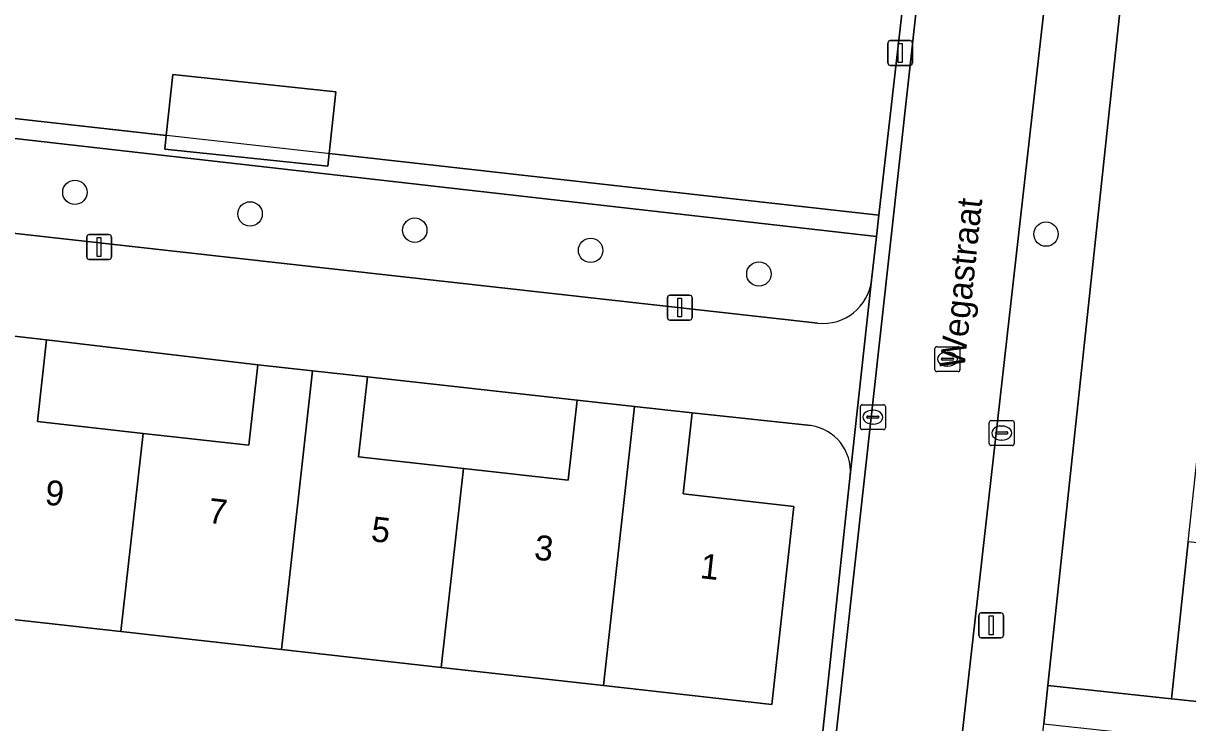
# Model space of a CAD drawing. Extents: x 161928 to 163071, y 386474 to 387428.
# Drawn here: x 162131.24 to 162177.94, y 386955.11 to 386983.15 of the extents above; entities that cross this region are included whole.
import ezdxf

# ---------------------------------------------------------------- set-up
doc = ezdxf.new("R2010")
doc.units = 0
for name, color, linetype in [('IMGEO_Boom', 7, 'Continuous'), ('IMGEO_Erf', 7, 'Continuous'), ('IMGEO_Groenvoorziening', 7, 'Continuous'), ('IMGEO_Haag', 7, 'Continuous'), ('IMGEO_Kolk', 7, 'Continuous'), ('IMGEO_Lichtmast', 7, 'Continuous'), ('IMGEO_Openbare_ruimte_label', 7, 'Continuous'), ('IMGEO_Pand', 7, 'Continuous'), ('IMGEO_Pand_nummerreeks', 7, 'Continuous'), ('IMGEO_Rijbaan_lokaal_open', 7, 'Continuous'), ('IMGEO_Rioolput', 7, 'Continuous'), ('IMGEO_Voetpad_open', 7, 'Continuous')]:
    doc.layers.add(name, color=color, linetype=linetype)

msp = doc.modelspace()

# ---------------------------------------------------------------- linework, layer by layer
at = {"layer": 'IMGEO_Boom'}
for centre in [(162133.311, 386976.375), (162140.338, 386975.511), (162146.943, 386974.86), (162172.257, 386974.701), (162153.993, 386974.049), (162160.742, 386973.102)]:
    msp.add_circle(centre, 0.489, dxfattribs=at)
at = {"layer": 'IMGEO_Erf'}
for points in [[(162179.889, 386980.353), (162180.525, 386986.295), (162181.184, 386992.453), (162181.804, 386998.248), (162181.992, 387000), (162182.414, 387003.937), (162177.44, 387004.467), (162176.963, 387000), (162172.334, 386956.598), (162177.289, 386956.069), (162177.963, 386962.367), (162178.601, 386968.327), (162179.255, 386974.437)], [(162132.178, 386970.465), (162131.811, 386967.181), (162136.048, 386966.707), (162140.285, 386966.233), (162140.646, 386969.464)], [(162145.047, 386968.972), (162144.69, 386965.776), (162148.892, 386965.306), (162153.093, 386964.836), (162153.452, 386968.047)]]:
    msp.add_lwpolyline(points, close=True, dxfattribs=at)
for points in [[(162131.63, 386987.411), (162125.153, 386988.143), (162118.693, 386988.873), (162109.184, 386989.948), (162108.279, 386981.822), (162117.837, 386980.804), (162130.648, 386979.367), (162136.977, 386978.659), (162137.235, 386981.096), (162143.771, 386980.405), (162143.509, 386977.927), (162165.555, 386975.46), (162167.511, 386992.682)], [(162162.828, 386967.021), (162158.07, 386967.531), (162157.707, 386964.281), (162162.148, 386963.785), (162161.259, 386955.842), (162154.507, 386956.597), (162147.999, 386957.326), (162141.594, 386958.042), (162135.159, 386958.762), (162128.668, 386959.489), (162122.196, 386960.213), (162115.733, 386960.936), (162108.941, 386961.696), (162109.832, 386969.663), (162114.38, 386969.154), (162114.747, 386972.438), (162109.157, 386973.068)], [(162106.981, 386971.336), (162105.127, 386954.086), (162111.551, 386953.32), (162111.902, 386956.457), (162115.148, 386956.094), (162114.794, 386952.933), (162162.272, 386947.379), (162162.618, 386948.375), (162164.401, 386965.029)]]:
    msp.add_lwpolyline(points, dxfattribs=at)
msp.add_arc((162162.57, 386965.2), 1.839, 354.6685, 81.9249, dxfattribs=at)
at = {"layer": 'IMGEO_Groenvoorziening'}
msp.add_lwpolyline([(162136.977, 386978.659), (162130.648, 386979.367), (162117.837, 386980.804), (162108.279, 386981.822), (162108.2, 386981.114), (162165.458, 386974.606), (162165.555, 386975.46), (162143.509, 386977.927), (162143.456, 386977.421), (162136.919, 386978.111)], close=True, dxfattribs=at)
for points in [[(162165.259, 386972.856), (162165.458, 386974.606), (162108.2, 386981.114)], [(162109.769, 386977.086), (162163.103, 386971.136)]]:
    msp.add_lwpolyline(points, dxfattribs=at)
msp.add_arc((162163.32, 386973.075), 1.952, 263.6208, 353.5431, dxfattribs=at)
at = {"layer": 'IMGEO_Haag'}
msp.add_lwpolyline([(162108.279, 386981.822), (162108.2, 386981.114), (162165.458, 386974.606), (162165.555, 386975.46), (162130.648, 386979.367), (162117.837, 386980.804)], close=True, dxfattribs=at)
at = {"layer": 'IMGEO_Kolk'}
for p, q in [((162164.89, 386967.862), (162165.742, 386967.862)), ((162164.815, 386966.936), (162164.815, 386967.788)), ((162165.074, 386967.356), (162165.074, 386967.368)), ((162165.117, 386967.405), (162165.515, 386967.405)), ((162165.303, 386967.642), (162165.328, 386967.642)), ((162165.558, 386967.368), (162165.558, 386967.356)), ((162165.816, 386967.788), (162165.816, 386966.936)), ((162165.512, 386967.319), (162165.114, 386967.319)), ((162165.326, 386967.082), (162165.301, 386967.082)), ((162169.978, 386966.299), (162169.978, 386967.151)), ((162170.053, 386967.225), (162170.905, 386967.225)), ((162170.466, 386967.005), (162170.491, 386967.005)), ((162170.979, 386967.151), (162170.979, 386966.299)), ((162165.742, 386966.862), (162164.89, 386966.862)), ((162170.237, 386966.719), (162170.237, 386966.731)), ((162170.675, 386966.682), (162170.277, 386966.682)), ((162170.28, 386966.768), (162170.678, 386966.768)), ((162170.489, 386966.445), (162170.464, 386966.445)), ((162170.721, 386966.731), (162170.721, 386966.719)), ((162170.905, 386966.225), (162170.053, 386966.225))]:
    msp.add_line(p, q, dxfattribs=at)
for points in [[(162164.89, 386967.862), (162165.742, 386967.862)], [(162164.815, 386966.936), (162164.815, 386967.788)], [(162165.816, 386967.788), (162165.816, 386966.936)], [(162169.978, 386966.299), (162169.978, 386967.151)], [(162170.053, 386967.225), (162170.905, 386967.225)], [(162170.979, 386967.151), (162170.979, 386966.299)], [(162165.742, 386966.862), (162164.89, 386966.862)], [(162170.905, 386966.225), (162170.053, 386966.225)]]:
    msp.add_lwpolyline(points, dxfattribs=at)
for centre, radius, start, end in [((162164.892, 386967.786), 0.0765, 91.552, 178.448), ((162164.892, 386967.786), 0.0765, 91.552, 178.448), ((162165.74, 386967.786), 0.0765, 1.552, 88.448), ((162165.74, 386967.786), 0.0765, 1.552, 88.448), ((162165.114, 386967.365), 0.0403, 85.8775, 175.7526), ((162165.519, 386967.367), 0.0386, 1.7309, 96.639), ((162164.892, 386966.938), 0.0765, 181.552, 268.448), ((162164.892, 386966.938), 0.0765, 181.552, 268.448), ((162165.111, 386967.355), 0.0366, 178.938, 274.7102), ((162165.515, 386967.362), 0.043, 264.8664, 352.4533), ((162165.74, 386966.938), 0.0765, 271.552, 358.448), ((162165.74, 386966.938), 0.0765, 271.552, 358.448), ((162170.055, 386967.149), 0.0765, 91.552, 178.448), ((162170.055, 386967.149), 0.0765, 91.552, 178.448), ((162170.903, 386967.149), 0.0765, 1.552, 88.448), ((162170.903, 386967.149), 0.0765, 1.552, 88.448), ((162170.277, 386966.728), 0.0403, 85.8775, 175.7526), ((162170.274, 386966.718), 0.0366, 178.938, 274.7102), ((162170.678, 386966.725), 0.043, 264.8664, 352.4533), ((162170.682, 386966.73), 0.0386, 1.7309, 96.639), ((162170.055, 386966.301), 0.0765, 181.552, 268.448), ((162170.055, 386966.301), 0.0765, 181.552, 268.448), ((162170.903, 386966.301), 0.0765, 271.552, 358.448), ((162170.903, 386966.301), 0.0765, 271.552, 358.448)]:
    msp.add_arc(centre, radius, start, end, dxfattribs=at)
for centre, major_axis, ratio, start_param, end_param in [((162165.302, 386967.362), (-0.387, 0.002), 0.722429, 4.712389, 7.853982), ((162165.327, 386967.362), (-0.39, 0.002), 0.717154, 1.570796, 4.712389), ((162170.465, 386966.725), (-0.387, 0.002), 0.722429, 4.712389, 7.853982), ((162170.49, 386966.725), (-0.39, 0.002), 0.717154, 1.570796, 4.712389)]:
    msp.add_ellipse(centre, major_axis=major_axis, ratio=ratio, start_param=start_param, end_param=end_param, dxfattribs=at)
at = {"layer": 'IMGEO_Lichtmast'}
for p, q in [((162165.912, 386981.563), (162165.912, 386982.363)), ((162165.912, 386982.363), (162165.912, 386981.563)), ((162166.012, 386982.463), (162166.802, 386982.463)), ((162166.802, 386982.463), (162166.012, 386982.463)), ((162166.902, 386982.363), (162166.902, 386981.563)), ((162166.902, 386981.563), (162166.902, 386982.363)), ((162166.802, 386981.463), (162166.012, 386981.463)), ((162166.012, 386981.463), (162166.802, 386981.463)), ((162133.786, 386973.785), (162133.786, 386974.585)), ((162133.786, 386974.585), (162133.786, 386973.785)), ((162133.886, 386974.685), (162134.676, 386974.685)), ((162134.676, 386974.685), (162133.886, 386974.685)), ((162134.776, 386974.585), (162134.776, 386973.785)), ((162134.776, 386973.785), (162134.776, 386974.585)), ((162134.676, 386973.685), (162133.886, 386973.685)), ((162133.886, 386973.685), (162134.676, 386973.685)), ((162157.072, 386971.354), (162157.072, 386972.154)), ((162157.072, 386972.154), (162157.072, 386971.354)), ((162157.172, 386972.254), (162157.962, 386972.254)), ((162157.962, 386972.254), (162157.172, 386972.254)), ((162158.062, 386972.154), (162158.062, 386971.354)), ((162158.062, 386971.354), (162158.062, 386972.154)), ((162157.962, 386971.254), (162157.172, 386971.254)), ((162157.172, 386971.254), (162157.962, 386971.254)), ((162169.661, 386959.514), (162170.451, 386959.514)), ((162170.451, 386959.514), (162169.661, 386959.514)), ((162169.561, 386958.614), (162169.561, 386959.414)), ((162169.561, 386959.414), (162169.561, 386958.614)), ((162170.551, 386959.414), (162170.551, 386958.614)), ((162170.551, 386958.614), (162170.551, 386959.414)), ((162170.451, 386958.514), (162169.661, 386958.514)), ((162169.661, 386958.514), (162170.451, 386958.514))]:
    msp.add_line(p, q, dxfattribs=at)
for points in [[(162166.332, 386982.338), (162166.482, 386982.338), (162166.482, 386981.588), (162166.332, 386981.588), (162166.332, 386982.338)], [(162134.206, 386974.56), (162134.356, 386974.56), (162134.356, 386973.81), (162134.206, 386973.81), (162134.206, 386974.56)], [(162157.492, 386972.129), (162157.642, 386972.129), (162157.642, 386971.379), (162157.492, 386971.379), (162157.492, 386972.129)], [(162169.981, 386959.389), (162170.131, 386959.389), (162170.131, 386958.639), (162169.981, 386958.639), (162169.981, 386959.389)]]:
    msp.add_lwpolyline(points, dxfattribs=at)
for centre, start, end in [((162166.012, 386982.363), 90, 180), ((162166.012, 386982.363), 90, 180), ((162166.802, 386982.363), 0, 90), ((162166.802, 386982.363), 360, 90), ((162166.012, 386981.563), 180, 270), ((162166.012, 386981.563), 180, 270), ((162166.802, 386981.563), 270, 0), ((162166.802, 386981.563), 270, 0), ((162133.886, 386974.585), 90, 180), ((162133.886, 386974.585), 90, 180), ((162134.676, 386974.585), 0, 90), ((162134.676, 386974.585), 360, 90), ((162133.886, 386973.785), 180, 270), ((162133.886, 386973.785), 180, 270), ((162134.676, 386973.785), 270, 0), ((162134.676, 386973.785), 270, 0), ((162157.172, 386972.154), 90, 180), ((162157.172, 386972.154), 90, 180), ((162157.962, 386972.154), 0, 90), ((162157.962, 386972.154), 360, 90), ((162157.172, 386971.354), 180, 270), ((162157.172, 386971.354), 180, 270), ((162157.962, 386971.354), 270, 0), ((162157.962, 386971.354), 270, 0), ((162169.661, 386959.414), 90, 180), ((162169.661, 386959.414), 90, 180), ((162170.451, 386959.414), 0, 90), ((162170.451, 386959.414), 360, 90), ((162169.661, 386958.614), 180, 270), ((162169.661, 386958.614), 180, 270), ((162170.451, 386958.614), 270, 0), ((162170.451, 386958.614), 270, 0)]:
    msp.add_arc(centre, 0.1, start, end, dxfattribs=at)
at = {"layer": 'IMGEO_Pand'}
for points in [[(162137.235, 386981.096), (162136.977, 386978.659), (162136.919, 386978.111), (162143.456, 386977.421), (162143.509, 386977.927), (162143.771, 386980.405)], [(162129.925, 386970.717), (162128.668, 386959.489), (162135.159, 386958.762), (162136.048, 386966.707), (162131.811, 386967.181), (162132.178, 386970.465)], [(162140.646, 386969.464), (162140.285, 386966.233), (162136.048, 386966.707), (162135.159, 386958.762), (162141.594, 386958.042), (162142.845, 386969.218)], [(162142.845, 386969.218), (162141.594, 386958.042), (162147.999, 386957.326), (162148.892, 386965.306), (162144.69, 386965.776), (162145.047, 386968.972)], [(162153.452, 386968.047), (162153.093, 386964.836), (162148.892, 386965.306), (162147.999, 386957.326), (162154.507, 386956.597), (162155.76, 386967.789)], [(162155.76, 386967.789), (162154.507, 386956.597), (162161.259, 386955.842), (162162.148, 386963.785), (162157.707, 386964.281), (162158.07, 386967.531)], [(162177.963, 386962.367), (162177.289, 386956.069), (162182.261, 386955.54), (162185.872, 386955.155), (162186.546, 386961.449)]]:
    msp.add_lwpolyline(points, close=True, dxfattribs=at)
at = {"layer": 'IMGEO_Rijbaan_lokaal_open'}
msp.add_lwpolyline([(162177.594, 387078.928), (162177.465, 387077.766), (162163.864, 386954.91), (162163.382, 386950.665), (162168.395, 386950.077), (162168.956, 386955.24), (162174.417, 387003.525), (162174.44, 387003.78), (162174.518, 387004.265), (162176.148, 387018.705)], dxfattribs=at)
at = {"layer": 'IMGEO_Rioolput'}
for p, q in [((162167.877, 386970.188), (162168.729, 386970.188)), ((162167.802, 386969.262), (162167.802, 386970.114)), ((162168.061, 386969.682), (162168.061, 386969.694)), ((162168.104, 386969.731), (162168.502, 386969.731)), ((162168.29, 386969.968), (162168.315, 386969.968)), ((162168.545, 386969.694), (162168.545, 386969.682)), ((162168.803, 386970.114), (162168.803, 386969.262)), ((162168.499, 386969.645), (162168.101, 386969.645)), ((162168.313, 386969.408), (162168.288, 386969.408)), ((162168.729, 386969.188), (162167.877, 386969.188))]:
    msp.add_line(p, q, dxfattribs=at)
for points in [[(162167.877, 386970.188), (162168.729, 386970.188)], [(162167.802, 386969.262), (162167.802, 386970.114)], [(162168.803, 386970.114), (162168.803, 386969.262)], [(162168.729, 386969.188), (162167.877, 386969.188)]]:
    msp.add_lwpolyline(points, dxfattribs=at)
for centre, radius, start, end in [((162167.879, 386970.112), 0.0765, 91.552, 178.448), ((162167.879, 386970.112), 0.0765, 91.552, 178.448), ((162168.727, 386970.112), 0.0765, 1.552, 88.448), ((162168.727, 386970.112), 0.0765, 1.552, 88.448), ((162168.101, 386969.691), 0.0403, 85.8775, 175.7526), ((162168.506, 386969.693), 0.0386, 1.7309, 96.639), ((162167.879, 386969.264), 0.0765, 181.552, 268.448), ((162167.879, 386969.264), 0.0765, 181.552, 268.448), ((162168.098, 386969.681), 0.0366, 178.938, 274.7102), ((162168.502, 386969.688), 0.043, 264.8664, 352.4533), ((162168.727, 386969.264), 0.0765, 271.552, 358.448), ((162168.727, 386969.264), 0.0765, 271.552, 358.448)]:
    msp.add_arc(centre, radius, start, end, dxfattribs=at)
for centre, major_axis, ratio, start_param, end_param in [((162168.289, 386969.688), (-0.387, 0.002), 0.722429, 4.712389, 7.853982), ((162168.314, 386969.688), (-0.39, 0.002), 0.717154, 1.570796, 4.712389)]:
    msp.add_ellipse(centre, major_axis=major_axis, ratio=ratio, start_param=start_param, end_param=end_param, dxfattribs=at)
at = {"layer": 'IMGEO_Voetpad_open'}
for points in [[(162176.696, 387075.008), (162174.898, 387059.249), (162174.539, 387056.102), (162173.766, 387048.438), (162171.865, 387031.331), (162171.776, 387030.536), (162171.587, 387028.835), (162171.544, 387028.577), (162170.719, 387020.821), (162168.711, 387002.789), (162168.507, 387000.952), (162167.511, 386992.682), (162165.555, 386975.46), (162165.458, 386974.606), (162165.259, 386972.856), (162164.401, 386965.029), (162162.618, 386948.375), (162163.149, 386948.547), (162163.382, 386950.665), (162163.864, 386954.91), (162177.465, 387077.766)], [(162176.963, 387000), (162177.44, 387004.467), (162177.59, 387005.919), (162177.84, 387008.247), (162177.394, 387008.043), (162176.967, 387007.8), (162176.564, 387007.52), (162176.187, 387007.205), (162175.841, 387006.858), (162175.526, 387006.481), (162175.247, 387006.077), (162175.004, 387005.651), (162174.801, 387005.204), (162174.638, 387004.741), (162174.518, 387004.265), (162174.44, 387003.78), (162174.417, 387003.525), (162168.956, 386955.24), (162168.395, 386950.077), (162168.226, 386948.441)], [(162168.532, 386945.38), (162172.651, 386944.931), (162172.508, 386944.96), (162172.368, 386945.002), (162172.232, 386945.055), (162172.101, 386945.121), (162171.977, 386945.198), (162171.86, 386945.286), (162171.752, 386945.385), (162171.653, 386945.492), (162171.564, 386945.608), (162171.485, 386945.731), (162171.418, 386945.861), (162171.363, 386945.996), (162171.32, 386946.136), (162171.289, 386946.279), (162171.272, 386946.424), (162171.267, 386946.57), (162171.276, 386946.716), (162172.17, 386955.064), (162172.334, 386956.598), (162176.963, 387000)], [(162163.103, 386971.136), (162109.769, 386977.086)], [(162109.157, 386973.068), (162114.747, 386972.438), (162116.992, 386972.187), (162119.239, 386971.936), (162127.672, 386970.969), (162129.925, 386970.717), (162132.178, 386970.465), (162140.646, 386969.464), (162142.845, 386969.218), (162145.047, 386968.972), (162153.452, 386968.047), (162155.76, 386967.789), (162158.07, 386967.531), (162162.828, 386967.021)], [(162164.401, 386965.029), (162165.259, 386972.856)], [(162182.261, 386955.54), (162177.289, 386956.069), (162172.334, 386956.598), (162172.17, 386955.064), (162180.57, 386954.161)]]:
    msp.add_lwpolyline(points, dxfattribs=at)
for centre, radius, start, end in [((162163.32, 386973.075), 1.952, 263.6208, 353.5431), ((162162.57, 386965.2), 1.839, 354.6685, 81.9249)]:
    msp.add_arc(centre, radius, start, end, dxfattribs=at)

# ---------------------------------------------------------------- texts
at = {"layer": 'IMGEO_Openbare_ruimte_label'}
msp.add_text('Wegastraat', height=1, rotation=83.97, dxfattribs=at).set_placement((162168.982, 386969.285))
at = {"layer": 'IMGEO_Pand_nummerreeks'}
for s, p in [('9', (162132.08, 386963.863)), ('7', (162138.62, 386963.128)), ('5', (162145.159, 386962.393)), ('3', (162151.699, 386961.658)), ('1', (162158.351, 386960.911))]:
    msp.add_text(s, height=1, rotation=353.5894, dxfattribs=at).set_placement(p)

doc.saveas('drawing.dxf')
